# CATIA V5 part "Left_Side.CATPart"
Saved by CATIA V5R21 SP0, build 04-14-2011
Part number: Left_Side
Bounding box of the stored display mesh (mm): x -172.8 to 2.8, y 0 to 2.8, z -5 to 133.511
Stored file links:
  C:\Users\Pouria\Desktop\Box\Left_Side.CATPart
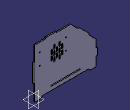
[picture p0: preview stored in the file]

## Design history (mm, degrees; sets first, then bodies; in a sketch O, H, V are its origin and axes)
Body1 (main body)
  Sketch1 on zx-plane, origin (0, 0, 0), H (-1, 0, 0), V (0, 0, 1)
    line L1 (0, 0) -> (0, 40)
    line L2 (0, 130.7107) -> (30, 130.7107)
    point P2 (99.2893, 130.7107)
    line L3 (99.2893, 130.7107) -> (120.5025, 109.4975)
    point P3 (170, 60)
    line L4 (170, 60) -> (170, 40)
    point P4 (170, 0)
    line L5 (147.8, 0) -> (22.2, 0)
    line L6 (45, 12.8) -> (125, 12.8)
    line L7 (125, 12.8) -> (125, 10)
    line L8 (125, 10) -> (45, 10)
    line L9 (45, 10) -> (45, 12.8)
    line L10 (147.8, 0) -> (152.8, -5)
    line L11 (152.8, -5) -> (170, -5)
    point P11 (170, -5)
    line L12 (170, -5) -> (170, 0)
    line L13 (0, 0) -> (0, -5)
    line L14 (0, -5) -> (17.2, -5)
    line L15 (17.2, -5) -> (22.2, 0)
    circle A1 centre (14, 106.7107) radius 1.5
    point P15 (14, 106.7107)
    circle A2 centre (14, 74.7107) radius 1.5
    point P16 (14, 74.7107)
    circle A3 centre (86, 106.7107) radius 1.5
    point P17 (86, 106.7107)
    circle A4 centre (86, 74.7107) radius 1.5
    point P18 (86, 74.7107)
    line L16 (120.5025, 109.4975) -> (122.4824, 111.4774)
    line L17 (122.4824, 111.4774) -> (150.7667, 83.1931)
    line L18 (150.7667, 83.1931) -> (148.7868, 81.2132)
    point P22 (148.7868, 81.2132)
    line L19 (148.7868, 81.2132) -> (170, 60)
    line L20 (30, 130.7107) -> (30, 133.5107)
    line L21 (30, 133.5107) -> (60, 133.5107)
    line L22 (60, 133.5107) -> (60, 130.7107)
    point P26 (60, 130.7107)
    line L23 (170, 40) -> (172.8, 40)
    line L24 (172.8, 40) -> (172.8, 20)
    line L25 (172.8, 20) -> (170, 20)
    point P30 (170, 20)
    line L26 (170, 20) -> (170, 0)
    line L27 (60, 130.7107) -> (99.2893, 130.7107)
    point P31 (0, 90)
    line L28 (0, 90) -> (-2.8, 90)
    line L29 (-2.8, 90) -> (-2.8, 40)
    line L30 (-2.8, 40) -> (0, 40)
    line L31 (0, 90) -> (0, 130.7107)
    length L6 = 80
    distance L8 L6 = 2.8
    distance L7 L4 = 45
    distance L8 L5 = 10
    angle L3 L4 = 135
    angle L10 L5 = 45
    length L12 = 5
    length L11 = 17.2
    length L14 = 17.2
    length L13 = 5
    angle L5 L15 = 45
    distance P4 O = 170
    length L5 = 125.6
    distance P18 P17 H = 0
    distance P16 P15 H = 0
    distance P17 P15 V = 0
    distance P18 P16 V = 0
    distance P18 P16 = 72
    distance P15 P16 = 32
    radius A1 = 1.5
    radius A3 = 1.5
    radius A4 = 1.5
    radius A2 = 1.5
    distance P15 L2 = 24
    distance P15 L1 = 14
    length L17 = 40
    distance L17 L3 = 2.8
    distance L18 P3 = 30
    distance P2 P3 = 100
    length L24 = 20
    length L23 = 2.8
    distance L25 L5 = 20
    distance P3 P4 = 60
    length L21 = 30
    distance L20 L1 = 30
    distance L21 L2 = 2.8
    length L29 = 50
    distance L5 L30 = 40
    distance L29 L1 = 2.8
    vertical: L1 V, L4 V, L7 V, L9 V, L12 V, L13 V, L20 V, L22 V, L24 V, L26 V, L29 V, L31 V
    horizontal: L2 H, L5 H, L6 H, L8 H, L11 H, L14 H, L21 H, L23 H, L25 H, L27 H, L28 H, L30 H
    coincidence: P4 H, P11 L4, L12 L4, L13 L1, P22 L3, L3 L19, P26 L2, P30 L4, L4 L26, L2 L27, P31 L1, L1 L31
    perpendicularity: L18 L3, L16 L3
  Pad1: profile Sketch1, direction (0, 1, 0), length 2.8
  Sketch2 on end face of Pad1, origin (0, 2.8, 0), H (-1, 0, 0), V (0, 0, 1)
    line L1 (77.5, 81.7107) -> (73.5, 81.7107)
    line L2 (73.5, 81.7107) -> (73.5, 69.7107)
    line L3 (73.5, 69.7107) -> (77.5, 69.7107)
    line L4 (77.5, 69.7107) -> (77.5, 81.7107)
    reference projected circle E1 centre (86, 74.7107) radius 1.5 from edge [end face of Pad1 | face of Pad1 from Sketch1.A4]
    reference projected circle E2 centre (86, 74.7107) radius 1.5 from edge [end face of Pad1 | face of Pad1 from Sketch1.A4]
    distance L3 E1 = 3.5
    distance L4 E2 = 10
    length L3 = 4
    length L2 = 12
    horizontal: L1 H, L3 H
    vertical: L2 V, L4 V
  Pocket1: profile Sketch2, direction (0, -1, 0), through (limit type 3)
  RectPattern1: of Pocket1, direction 1 instances 3, spacing 14, along edge [end face of Pad1 | face of Pad1 from Sketch1.L6], direction 2 instances 3, spacing 15, along edge [face of Pad1 from Sketch1.L29 | end face of Pad1] reversed
  Sketch3 on end face of Pad1, origin (0, 2.8, 0), H (-1, 0, 0), V (0, 0, 1)
    line L1 (66.5, 75.7107) -> (70.5, 75.7107)
    line L2 (70.5, 75.7107) -> (70.5, 63.7107)
    line L3 (70.5, 63.7107) -> (66.5, 63.7107)
    line L4 (66.5, 63.7107) -> (66.5, 75.7107)
    reference projected line E1 (73.5, 81.7107) -> (73.5, 69.7107) from edge [end face of Pad1 | face of Pocket1 from Sketch2.L2]
    reference projected line E2 (73.5, 69.7107) -> (77.5, 69.7107) from edge [end face of Pad1 | face of Pocket1 from Sketch2.L3]
    distance L2 E1 = 3
    length L2 = 12
    length L3 = 4
    distance L3 E2 = 6
    horizontal: L1 H, L3 H
    vertical: L2 V, L4 V
  Pocket2: profile Sketch3, direction (0, -1, 0), through (limit type 3)
  RectPattern2: of Pocket2, direction 1 instances 2, spacing 14, along edge [face of Pad1 from Sketch1.L27 | end face of Pad1], direction 2 instances 3, spacing 15, along edge [face of Pad1 from Sketch1.L31 | end face of Pad1] reversed
  Fillet1: radius 1, on edge [face of RectPattern1 | face of RectPattern1] (x32); edge [face of RectPattern2 | face of RectPattern2] (x20); edge [face of Pocket1 from Sketch2.L2 | face of Pocket1 from Sketch2.L1]; edge [face of Pocket2 from Sketch3.L4 | face of Pocket2 from Sketch3.L1]; edge [face of Pocket2 from Sketch3.L3 | face of Pocket2 from Sketch3.L4]; edge [face of Pocket1 from Sketch2.L3 | face of Pocket1 from Sketch2.L2]; edge [face of Pocket1 from Sketch2.L1 | face of Pocket1 from Sketch2.L4]; edge [face of Pocket2 from Sketch3.L1 | face of Pocket2 from Sketch3.L2]; edge [face of Pocket2 from Sketch3.L2 | face of Pocket2 from Sketch3.L3]; edge [face of Pocket1 from Sketch2.L4 | face of Pocket1 from Sketch2.L3]
  Sketch4 on end face of Pad1, origin (0, 2.8, 0), H (-1, 0, 0), V (0, 0, 1)
    line L1 (78.7193, 113.3506) -> (72.6493, 113.3506)
    line L2 (72.6493, 113.3506) -> (72.6493, 98.8904)
    line L3 (72.6493, 98.8904) -> (78.7193, 98.8904)
    line L4 (78.7193, 98.8904) -> (78.7193, 113.3506)
    point P5 (64.9239, 113.3506)
    line L5 (64.9239, 113.3506) -> (58.0813, 113.3506)
    line L6 (58.0813, 113.3506) -> (58.0813, 98.8904)
    line L7 (58.0813, 98.8904) -> (64.9239, 98.8904)
    line L8 (64.9239, 98.8904) -> (64.9239, 113.3506)
    point P7 (58.0813, 98.8904)
    line L9 (50.4662, 112.7031) -> (43.8443, 112.7031)
    line L10 (43.8443, 112.7031) -> (43.8443, 98.8904)
    line L11 (43.8443, 98.8904) -> (50.4662, 98.8904)
    line L12 (50.4662, 98.8904) -> (50.4662, 112.7031)
    point P11 (43.8443, 98.8904)
    horizontal: L1 H, L3 H, L5 H, L7 H, L9 H, L11 H
    vertical: L2 V, L4 V, L6 V, L8 V, L10 V, L12 V
    coincidence: P5 L1, P7 L3, P11 L3
  Pad2: profile Sketch4, direction (0, 1, 0), up to start face of Pad1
